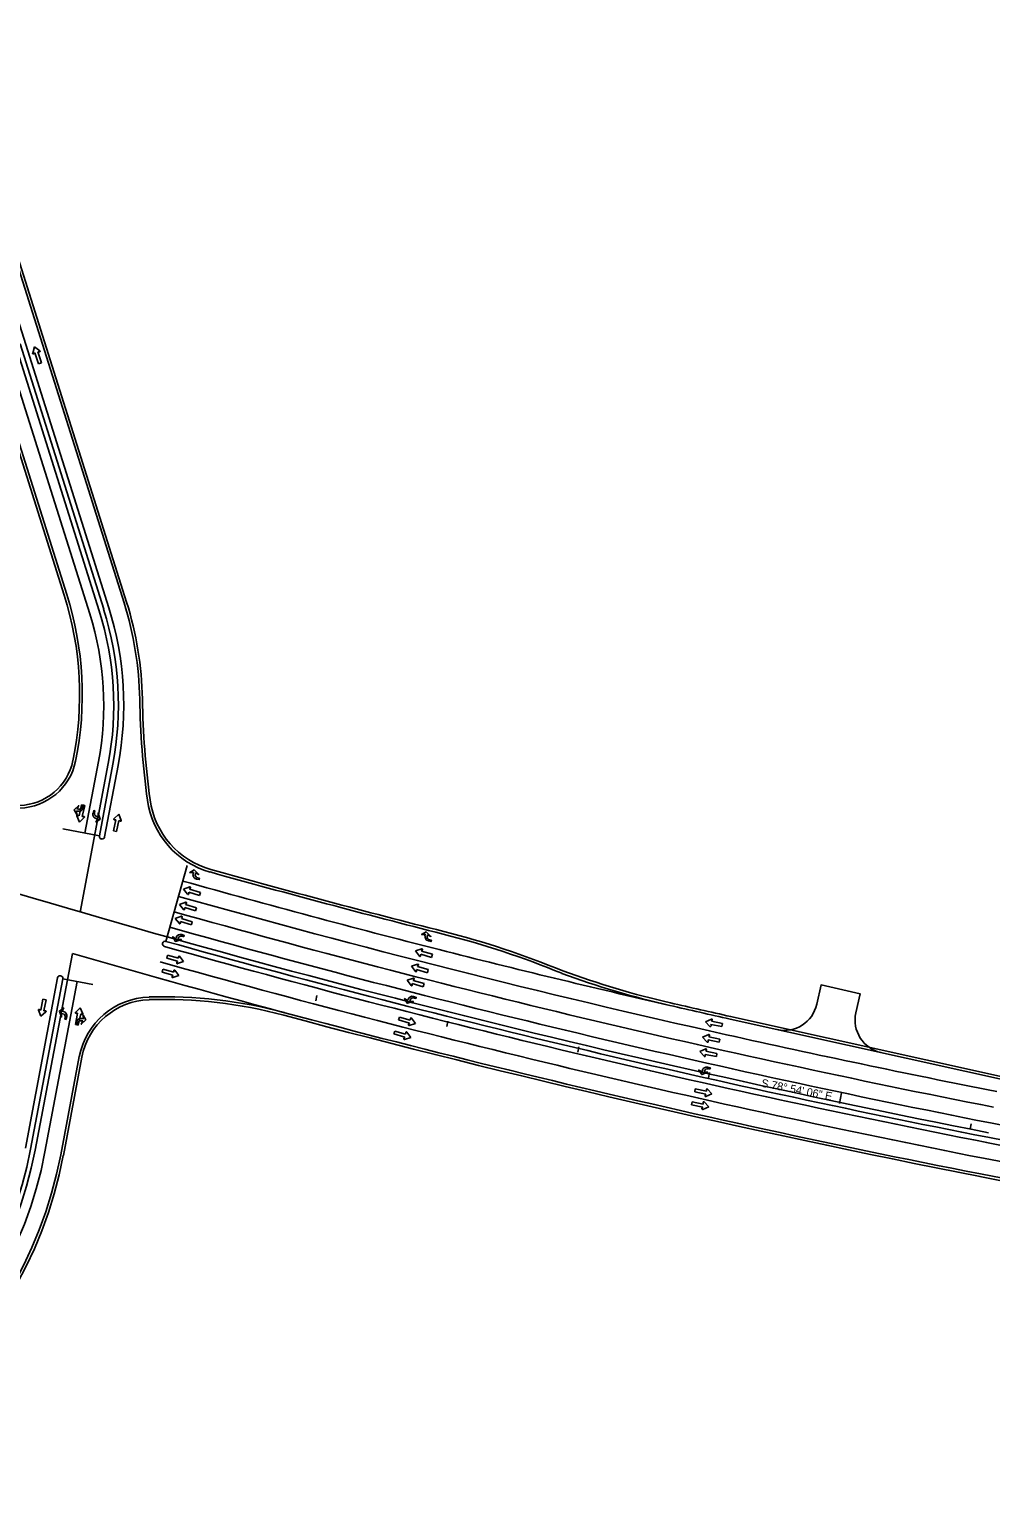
# Model space of a CAD drawing. Extents: x 1936748 to 1944587, y 778949 to 784066.
# Drawn here: x 1942950 to 1943671, y 779696 to 780801 of the extents above; entities that cross this region are included whole.
import ezdxf

# ---------------------------------------------------------------- set-up
doc = ezdxf.new("R2010")
doc.units = 0
for name, color, linetype in [('Default', 7, 'Continuous'), ('RD_HC_CL_Rel', 7, 'Continuous'), ('RD_HC_Data', 7, 'Continuous'), ('RD_HC_Data_Tic', 7, 'Continuous'), ('RD_PD_ALT1_LnLine', 7, 'Continuous'), ('RD_PD_ALT2_LnLine', 7, 'Continuous'), ('RD_PD_ALT3_LnLine', 7, 'Continuous'), ('RD_PD_Driveway', 7, 'Continuous'), ('RD_PD_Final_TrvlWay', 7, 'Continuous'), ('RD_PD_PaveShd', 7, 'Continuous')]:
    doc.layers.add(name, color=color, linetype=linetype)

msp = doc.modelspace()

# ---------------------------------------------------------------- linework, layer by layer
at = {"layer": 'Default'}
for p, q in [((1942953.8, 780563.7), (1942952.4, 780558.9)), ((1942953, 780558.4), (1942954.1, 780559.1)), ((1942957.8, 780560.7), (1942953.8, 780563.7)), ((1942954.1, 780559.1), (1942956.7, 780551)), ((1942956.3, 780559.8), (1942957.6, 780559.9)), ((1942958.9, 780551.7), (1942956.3, 780559.8)), ((1942957.8, 780560.7), (1942957.8, 780560.7)), ((1942956.7, 780551), (1942958.9, 780551.7)), ((1942989.1, 780220.3), (1942987.2, 780212)), ((1942991.4, 780219.8), (1942989.1, 780220.3)), ((1942989.4, 780218.9), (1942989.7, 780220.2)), ((1942989.5, 780211.5), (1942991.4, 780219.8)), ((1942998.8, 780214.4), (1942999.1, 780215.8)), ((1942985.5, 780212), (1942987.4, 780207.4)), ((1942985.5, 780212), (1942985.5, 780212)), ((1942987.2, 780212), (1942986.1, 780212.6)), ((1942987.4, 780207.4), (1942991, 780210.8)), ((1942990.7, 780211.5), (1942989.5, 780211.5)), ((1943014.8, 780209.2), (1943013, 780200.9)), ((1943017, 780213.3), (1943013.3, 780209.9)), ((1943013.6, 780209.2), (1943014.8, 780209.2)), ((1943015.2, 780200.4), (1943017.1, 780208.7)), ((1943018.8, 780208.7), (1943017, 780213.3)), ((1943017.1, 780208.7), (1943018.3, 780208.1)), ((1943018.8, 780208.7), (1943018.8, 780208.7)), ((1943013, 780200.9), (1943015.2, 780200.4)), ((1943070.3, 780158.8), (1943065.5, 780157.2)), ((1943070.3, 780158.8), (1943070.3, 780158.8)), ((1943076.2, 780165.6), (1943077.5, 780165.3)), ((1943065.5, 780157.2), (1943068.6, 780153.3)), ((1943069.4, 780153.6), (1943069.5, 780154.8)), ((1943069.5, 780154.8), (1943077.6, 780152.4)), ((1943070.1, 780157.1), (1943070.8, 780158.2)), ((1943078.3, 780154.7), (1943070.1, 780157.1)), ((1943077.6, 780152.4), (1943078.3, 780154.7)), ((1943064, 780136.8), (1943059.3, 780135.2)), ((1943067.2, 780147.3), (1943062.5, 780145.7)), ((1943062.5, 780145.7), (1943065.6, 780141.8)), ((1943064, 780136.8), (1943064, 780136.8)), ((1943066.3, 780142.1), (1943066.4, 780143.3)), ((1943066.4, 780143.3), (1943074.6, 780140.9)), ((1943067.1, 780145.6), (1943067.7, 780146.7)), ((1943075.2, 780143.2), (1943067.1, 780145.6)), ((1943067.2, 780147.3), (1943067.2, 780147.3)), ((1943074.6, 780140.9), (1943075.2, 780143.2)), ((1943059.3, 780135.2), (1943062.4, 780131.3)), ((1943063.2, 780131.6), (1943063.2, 780132.9)), ((1943063.2, 780132.9), (1943071.4, 780130.4)), ((1943063.9, 780135.1), (1943064.5, 780136.2)), ((1943072.1, 780132.7), (1943063.9, 780135.1)), ((1943071.4, 780130.4), (1943072.1, 780132.7)), ((1943064.5, 780121.9), (1943065.8, 780121.5)), ((1943250.1, 780119.2), (1943251.4, 780118.9)), ((1943053.5, 780107.7), (1943052.9, 780105.5)), ((1943052.9, 780105.5), (1943061, 780103.1)), ((1943061.7, 780105.3), (1943053.5, 780107.7)), ((1943061.8, 780106.5), (1943061.7, 780105.3)), ((1943065.6, 780102.9), (1943062.5, 780106.8)), ((1943244.2, 780112.4), (1943239.5, 780110.8)), ((1943239.5, 780110.8), (1943242.6, 780106.9)), ((1943243.3, 780107.2), (1943243.4, 780108.5)), ((1943243.4, 780108.5), (1943251.6, 780106)), ((1943244, 780110.7), (1943244.7, 780111.8)), ((1943252.2, 780108.3), (1943244, 780110.7)), ((1943244.2, 780112.4), (1943244.2, 780112.4)), ((1943251.6, 780106), (1943252.2, 780108.3)), ((1943050, 780097.2), (1943049.4, 780095)), ((1943049.4, 780095), (1943057.5, 780092.6)), ((1943058.2, 780094.8), (1943050, 780097.2)), ((1943057.5, 780092.6), (1943056.9, 780091.5)), ((1943057.4, 780090.9), (1943062.1, 780092.4)), ((1943058.3, 780096), (1943058.2, 780094.8)), ((1943062.1, 780092.4), (1943059, 780096.3)), ((1943061, 780103.1), (1943060.4, 780102)), ((1943060.9, 780101.3), (1943065.6, 780102.9)), ((1943060.9, 780101.3), (1943060.9, 780101.3)), ((1943241.1, 780100.9), (1943236.4, 780099.3)), ((1943236.4, 780099.3), (1943239.5, 780095.4)), ((1943240.3, 780095.7), (1943240.3, 780096.9)), ((1943240.3, 780096.9), (1943248.5, 780094.5)), ((1943241, 780099.2), (1943241.6, 780100.3)), ((1943249.1, 780096.8), (1943241, 780099.2)), ((1943241.1, 780100.9), (1943241.1, 780100.9)), ((1943248.5, 780094.5), (1943249.1, 780096.8)), ((1943057.4, 780090.9), (1943057.4, 780090.9)), ((1943237.9, 780090.4), (1943233.2, 780088.8)), ((1943233.2, 780088.8), (1943236.3, 780085)), ((1943237.1, 780085.2), (1943237.1, 780086.5)), ((1943237.1, 780086.5), (1943245.3, 780084)), ((1943237.8, 780088.7), (1943238.4, 780089.8)), ((1943246, 780086.3), (1943237.8, 780088.7)), ((1943237.9, 780090.4), (1943237.9, 780090.4)), ((1943245.3, 780084), (1943246, 780086.3)), ((1942960.1, 780074.8), (1942958.4, 780066.4)), ((1942962.4, 780074.3), (1942960.1, 780074.8)), ((1942960.7, 780066), (1942962.4, 780074.3)), ((1943238.4, 780075.5), (1943239.7, 780075.1)), ((1942956.7, 780066.4), (1942958.6, 780061.9)), ((1942956.7, 780066.4), (1942956.7, 780066.4)), ((1942958.4, 780066.4), (1942957.3, 780067)), ((1942958.6, 780061.9), (1942962.3, 780065.3)), ((1942961.9, 780066), (1942960.7, 780066)), ((1942976.8, 780061), (1942976.5, 780059.7)), ((1942986.1, 780064.1), (1942984.4, 780055.8)), ((1942988.1, 780068.2), (1942984.5, 780064.8)), ((1942984.8, 780064.1), (1942986.1, 780064.1)), ((1942986.6, 780055.3), (1942988.4, 780063.7)), ((1942990.1, 780063.7), (1942988.1, 780068.2)), ((1942988.4, 780063.7), (1942989.5, 780063.1)), ((1942990.1, 780063.7), (1942990.1, 780063.7)), ((1943227.5, 780061.3), (1943226.8, 780059.1)), ((1943226.8, 780059.1), (1943235, 780056.7)), ((1943235.6, 780058.9), (1943227.5, 780061.3)), ((1943235.7, 780060.1), (1943235.6, 780058.9)), ((1943239.6, 780056.5), (1943236.5, 780060.4)), ((1943461.4, 780059.8), (1943456.9, 780057.8)), ((1943461.4, 780059.8), (1943461.4, 780059.8)), ((1943461.5, 780058.1), (1943462, 780059.2)), ((1942984.4, 780055.8), (1942986.6, 780055.3)), ((1942986.3, 780056.8), (1942986, 780055.4)), ((1943224, 780050.8), (1943223.3, 780048.6)), ((1943223.3, 780048.6), (1943231.5, 780046.2)), ((1943232.1, 780048.4), (1943224, 780050.8)), ((1943232.2, 780049.7), (1943232.1, 780048.4)), ((1943236, 780046), (1943232.9, 780049.9)), ((1943235, 780056.7), (1943234.3, 780055.6)), ((1943234.8, 780055), (1943239.6, 780056.5)), ((1943234.8, 780055), (1943234.8, 780055)), ((1943459.4, 780048.1), (1943454.8, 780046.1)), ((1943456.9, 780057.8), (1943460.3, 780054.2)), ((1943459.4, 780048.1), (1943459.4, 780048.1)), ((1943461.1, 780054.6), (1943461, 780055.8)), ((1943461, 780055.8), (1943469.3, 780054.1)), ((1943469.8, 780056.4), (1943461.5, 780058.1)), ((1943469.3, 780054.1), (1943469.8, 780056.4)), ((1943231.5, 780046.2), (1943230.8, 780045.1)), ((1943231.3, 780044.5), (1943236, 780046)), ((1943231.3, 780044.5), (1943231.3, 780044.5)), ((1943457.2, 780037.4), (1943452.6, 780035.4)), ((1943454.8, 780046.1), (1943458.3, 780042.5)), ((1943457.2, 780037.4), (1943457.2, 780037.4)), ((1943459, 780042.8), (1943459, 780044.1)), ((1943459, 780044.1), (1943467.3, 780042.4)), ((1943459.4, 780046.4), (1943460, 780047.5)), ((1943467.8, 780044.7), (1943459.4, 780046.4)), ((1943467.3, 780042.4), (1943467.8, 780044.7)), ((1943452.6, 780035.4), (1943456.1, 780031.8)), ((1943456.8, 780032.1), (1943456.7, 780033.3)), ((1943456.7, 780033.3), (1943465.1, 780031.7)), ((1943457.2, 780035.6), (1943457.7, 780036.8)), ((1943465.5, 780033.9), (1943457.2, 780035.6)), ((1943465.1, 780031.7), (1943465.5, 780033.9)), ((1943459, 780022.6), (1943460.3, 780022.2)), ((1943449.3, 780007.4), (1943448.9, 780005.2)), ((1943448.9, 780005.2), (1943457.2, 780003.5)), ((1943457.7, 780005.8), (1943449.3, 780007.4)), ((1943457.2, 780001.7), (1943461.8, 780003.7)), ((1943457.6, 780007), (1943457.7, 780005.8)), ((1943461.8, 780003.7), (1943458.4, 780007.3)), ((1943447, 779997.8), (1943446.5, 779995.5)), ((1943446.5, 779995.5), (1943454.9, 779993.8)), ((1943455.3, 779996.1), (1943447, 779997.8)), ((1943454.9, 779993.8), (1943454.3, 779992.7)), ((1943454.9, 779992.1), (1943459.4, 779994.1)), ((1943455.3, 779997.4), (1943455.3, 779996.1)), ((1943459.4, 779994.1), (1943456, 779997.7)), ((1943457.2, 780003.5), (1943456.7, 780002.3)), ((1943457.2, 780001.7), (1943457.2, 780001.7)), ((1943454.9, 779992.1), (1943454.9, 779992.1))]:
    msp.add_line(p, q, dxfattribs=at)
for points in [[(1942986.3, 780215.5), (1942985.3, 780215.7), (1942985.4, 780213), (1942983.4, 780216.5), (1942986.9, 780219.8), (1942985.7, 780217.3), (1942986.7, 780217.1)], [(1942989.7, 780220.2), (1942990.7, 780220), (1942990.3, 780218)], [(1942999.1, 780215.8), (1942998.2, 780216), (1942997.7, 780214)], [(1943000, 780210), (1943001.1, 780209.8), (1942999.8, 780207.4), (1943003.1, 780209.6), (1943001.5, 780214.2), (1943001.5, 780211.4), (1943000.5, 780211.7)], [(1943072.7, 780168.6), (1943072.9, 780169.6), (1943070.2, 780169.5), (1943073.6, 780171.5), (1943077, 780168.1), (1943074.6, 780169.3), (1943074.4, 780168.3)], [(1943077.5, 780165.3), (1943077.3, 780164.3), (1943075.3, 780164.7)], [(1943060, 780121), (1943059.7, 780120), (1943057.4, 780121.5), (1943059.4, 780118), (1943064, 780119.3), (1943061.3, 780119.5), (1943061.6, 780120.5)], [(1943065.8, 780121.5), (1943066.1, 780122.4), (1943064.2, 780123.1)], [(1943246.6, 780122.2), (1943246.8, 780123.2), (1943244.1, 780123.1), (1943247.6, 780125.1), (1943251, 780121.7), (1943248.5, 780122.9), (1943248.3, 780121.9)], [(1943251.4, 780118.9), (1943251.2, 780117.9), (1943249.2, 780118.3)], [(1943234, 780074.6), (1943233.6, 780073.6), (1943231.3, 780075.1), (1943233.3, 780071.6), (1943237.9, 780072.9), (1943235.2, 780073.1), (1943235.5, 780074.1)], [(1943239.7, 780075.1), (1943240.1, 780076), (1943238.1, 780076.7)], [(1942975.5, 780065.4), (1942974.5, 780065.6), (1942975.7, 780068.1), (1942972.4, 780065.8), (1942974.1, 780061.3), (1942974.1, 780064), (1942975.1, 780063.8)], [(1942976.5, 780059.7), (1942977.5, 780059.5), (1942977.9, 780061.5)], [(1942989.3, 780060.2), (1942990.3, 780060), (1942990.2, 780062.7), (1942992.2, 780059.3), (1942988.8, 780055.9), (1942990, 780058.4), (1942989, 780058.6)], [(1942986, 780055.4), (1942985, 780055.6), (1942985.4, 780057.7)], [(1943454.6, 780021.3), (1943454.4, 780020.2), (1943451.9, 780021.5), (1943454.2, 780018.2), (1943458.7, 780019.9), (1943456, 780019.9), (1943456.2, 780020.9)], [(1943460.3, 780022.2), (1943460.6, 780023.2), (1943458.6, 780023.7)]]:
    msp.add_lwpolyline(points, dxfattribs=at)
for centre, radius, start, end in [((1942952.8, 780558.8), 0.443, 162.8279, 303.291), ((1942957.5, 780560.3), 0.443, 272.6168, 53.103), ((1942987.1, 780218.7), 3.28, 257.287, 347.287), ((1942987.2, 780219.4), 2.3, 257.287, 347.287), ((1943000.8, 780213.2), 3.28, 165.8722, 255.8722), ((1943001, 780213.9), 2.3, 165.8722, 255.8722), ((1942985.9, 780212.2), 0.443, 61.9969, 202.4831), ((1942990.8, 780211.1), 0.443, 312.208, 92.6711), ((1943013.6, 780209.6), 0.443, 132.208, 272.6711), ((1943018.4, 780208.5), 0.443, 241.9969, 22.4831), ((1943070.4, 780158.4), 0.443, 328.1928, 108.6791), ((1943075.9, 780167.9), 3.28, 168.7617, 258.7617), ((1943076.6, 780167.8), 2.3, 168.7617, 258.7617), ((1943069, 780153.6), 0.443, 218.4039, 358.867), ((1943064.2, 780136.4), 0.443, 328.1928, 108.6791), ((1943065.9, 780142.1), 0.443, 218.4039, 358.867), ((1943067.3, 780146.9), 0.443, 328.1928, 108.6791), ((1943062.7, 780131.6), 0.443, 218.4039, 358.867), ((1943063.1, 780120), 3.28, 71.3683, 161.3683), ((1943063.8, 780119.7), 2.3, 71.3683, 161.3683), ((1943249.9, 780121.6), 3.28, 168.7617, 258.7617), ((1943250.5, 780121.4), 2.3, 168.7617, 258.7617), ((1943062.2, 780106.5), 0.443, 38.4039, 178.867), ((1943242.9, 780107.2), 0.443, 218.4039, 358.867), ((1943244.3, 780112), 0.443, 328.1928, 108.6791), ((1943058.7, 780096.1), 0.443, 38.4039, 178.867), ((1943060.8, 780101.7), 0.443, 148.1928, 288.6791), ((1943239.8, 780095.7), 0.443, 218.4039, 358.867), ((1943241.3, 780100.5), 0.443, 328.1928, 108.6791), ((1943057.3, 780091.3), 0.443, 148.1928, 288.6791), ((1943236.7, 780085.2), 0.443, 218.4039, 358.867), ((1943238.1, 780090), 0.443, 328.1928, 108.6791), ((1943237.1, 780073.6), 3.28, 71.3683, 161.3683), ((1943237.7, 780073.3), 2.3, 71.3683, 161.3683), ((1942957.1, 780066.6), 0.443, 63.0465, 203.5327), ((1942962, 780065.6), 0.443, 313.2576, 93.7207), ((1942974.6, 780061.5), 2.3, 346.9217, 76.9217), ((1942974.8, 780062.2), 3.28, 346.9217, 76.9217), ((1942984.8, 780064.5), 0.443, 133.2576, 273.7207), ((1942988.6, 780057), 3.28, 78.3365, 168.3365), ((1942989.7, 780063.5), 0.443, 243.0465, 23.5327), ((1943236.1, 780060.2), 0.443, 38.4039, 178.867), ((1943461.6, 780059.4), 0.443, 333.301, 113.7872), ((1942988.5, 780056.3), 2.3, 78.3365, 168.3365), ((1943232.6, 780049.7), 0.443, 38.4039, 178.867), ((1943234.7, 780055.4), 0.443, 148.1928, 288.6791), ((1943459.6, 780047.7), 0.443, 333.301, 113.7872), ((1943460.6, 780054.5), 0.443, 223.5121, 3.9752), ((1943231.2, 780044.9), 0.443, 148.1928, 288.6791), ((1943457.4, 780037), 0.443, 333.301, 113.7872), ((1943458.6, 780042.8), 0.443, 223.5121, 3.9752), ((1943456.4, 780032.1), 0.443, 223.5121, 3.9752), ((1943457.8, 780020.5), 3.28, 76.4764, 166.4764), ((1943458.5, 780020.3), 2.3, 76.4764, 166.4764), ((1943458.1, 780007), 0.443, 43.5121, 183.9752), ((1943454.7, 779992.5), 0.443, 153.301, 293.7872), ((1943455.7, 779997.4), 0.443, 43.5121, 183.9752), ((1943457.1, 780002.1), 0.443, 153.301, 293.7872)]:
    msp.add_arc(centre, radius, start, end, dxfattribs=at)
at = {"layer": 'RD_HC_CL_Rel'}
for p, q in [((1942610.6, 781606.5), (1943002.3, 780365.8)), ((1943009.1, 780251.3), (1942988, 780140)), ((1942982.2, 780108.9), (1942954.2, 779961.6))]:
    msp.add_line(p, q, dxfattribs=at)
for centre, radius, start, end in [((1942778.2, 780295.1), 235, 349.2715, 17.5247), ((1945184.2, 787697.4), 7870, 252.6501, 258.90156), ((1942659.5, 780017.4), 300, 267.5865, 349.2715)]:
    msp.add_arc(centre, radius, start, end, dxfattribs=at)
at = {"layer": 'RD_HC_Data_Tic'}
for p, q in [((1943164.8, 780073.5), (1943165.6, 780077.5)), ((1943263, 780054.3), (1943263.7, 780058.2)), ((1943361.1, 780035), (1943361.9, 780039)), ((1943459.2, 780015.8), (1943460, 780019.7)), ((1943557.4, 779996.5), (1943558.9, 780004.4)), ((1943655.5, 779977.3), (1943656.3, 779981.2))]:
    msp.add_line(p, q, dxfattribs=at)
at = {"layer": 'RD_PD_ALT1_LnLine'}
for p, q in [((1942932.4, 780562.4), (1942995.2, 780363.6)), ((1943001.8, 780252.7), (1942991.6, 780199.1)), ((1942985.8, 780087.9), (1942961.6, 779960.2)), ((1943670.7, 779981.9), (1943888.6, 779939.2)), ((1943665.5, 779955.5), (1944051.2, 779879.8))]:
    msp.add_line(p, q, dxfattribs=at)
for centre, radius, start, end in [((1942778.2, 780295.1), 227.5, 349.2715, 17.5247), ((1945184.2, 787697.4), 7826.5, 254.29042, 255.74647), ((1945184.2, 787697.4), 7838.5, 254.29042, 257.38869), ((1945184.2, 787697.4), 7850.5, 254.29042, 258.90156), ((1945184.2, 787697.4), 7862.5, 254.29042, 258.90156), ((1945184.2, 787697.4), 7826.5, 255.74647, 257.04964), ((1945184.2, 787697.4), 7889.5, 254.29042, 258.90156), ((1945184.2, 787697.4), 7838.5, 257.38869, 258.90156), ((1942659.5, 780017.4), 307.5, 267.5865, 349.2715)]:
    msp.add_arc(centre, radius, start, end, dxfattribs=at)
at = {"layer": 'RD_PD_ALT2_LnLine'}
for p, q in [((1943002.4, 780197.1), (1942975, 780202.3)), ((1943052.3, 780118), (1943068.3, 780174.8)), ((1942975, 780089.9), (1942997.6, 780085.7))]:
    msp.add_line(p, q, dxfattribs=at)
at = {"layer": 'RD_PD_ALT3_LnLine'}
for p, q in [((1942880.1, 780777.7), (1943009.5, 780368.1)), ((1942942.9, 780565.8), (1943005.7, 780366.9)), ((1943012.6, 780250.7), (1943002.4, 780197.1)), ((1943016.5, 780249.9), (1943006.3, 780196.3)), ((1942971.1, 780090.7), (1942946.9, 779963)), ((1942975, 780089.9), (1942950.8, 779962.2)), ((1943668.6, 779971.2), (1943886.4, 779928.4)), ((1943667.8, 779967.2), (1944053.5, 779891.6))]:
    msp.add_line(p, q, dxfattribs=at)
for centre, radius, start, end in [((1942778.2, 780295.1), 238.5, 349.2715, 17.5247), ((1942778.2, 780295.1), 242.5, 349.2715, 17.5247), ((1943004.4, 780196.7), 2, 169.2715, 349.2715), ((1943051.8, 780116.1), 2, 74.2904, 254.2904), ((1945184.2, 787697.4), 7873.5, 254.29042, 258.90156), ((1945184.2, 787697.4), 7877.5, 254.29042, 258.90156), ((1942973, 780090.3), 2, 349.2715, 169.2715), ((1942659.5, 780017.4), 296.5, 267.5865, 349.2715)]:
    msp.add_arc(centre, radius, start, end, dxfattribs=at)
at = {"layer": 'RD_PD_Driveway'}
msp.add_lwpolyline([(1943540.4, 780070.9), (1943543.6, 780085.3), (1943572.9, 780078.8), (1943569.7, 780064.4)], dxfattribs=at)
for centre, start, end in [((1943516, 780076.3), 257.4946, 347.4946), ((1943594.1, 780059), 167.4946, 257.4946)]:
    msp.add_arc(centre, 25, start, end, dxfattribs=at)
at = {"layer": 'RD_PD_Final_TrvlWay'}
for p, q in [((1942891.5, 780781.5), (1943020.9, 780371.7)), ((1942854.3, 780769.7), (1942978, 780378.1)), ((1943475.4, 780059.7), (1944061, 779929.8)), ((1942987.3, 780031.6), (1942973.4, 779957.9)), ((1943663.2, 779943.7), (1944048.9, 779868))]:
    msp.add_line(p, q, dxfattribs=at)
for centre, radius, start, end in [((1942739.6, 780302.8), 250, 348.5083, 17.5247), ((1942778.2, 780295.1), 254.5, 0.9931, 17.5247), ((1943672.6, 780310.6), 640, 180.9931, 187.7904), ((1942941.5, 780261.8), 43.9, 271.5515, 348.5083), ((1943102.9, 780232.6), 65, 187.7904, 254.4209), ((1945184.2, 787697.4), 7814.5, 254.42086, 255.74647), ((1943095.2, 779474.1), 670, 67.716, 75.7465), ((1945184.2, 787697.4), 7901.5, 253.81826, 258.90156), ((1943580.4, 780722.9), 670, 249.8217, 257.0496), ((1943041.4, 780021.3), 55, 91.8035, 169.2715), ((1943050.7, 779726.5), 350, 75.0153, 91.8035), ((1945184.2, 787697.4), 7826.5, 257.04964, 257.38869), ((1942659.5, 780017.4), 319.5, 267.5865, 349.2715)]:
    msp.add_arc(centre, radius, start, end, dxfattribs=at)
at = {"layer": 'RD_PD_PaveShd'}
for p, q in [((1942893.4, 780782.1), (1943022.8, 780372.3)), ((1942852.4, 780769.1), (1942976.1, 780377.5)), ((1943475.8, 780061.7), (1944061.4, 779931.8)), ((1942989.3, 780031.2), (1942975.4, 779957.6)), ((1943662.8, 779941.7), (1944048.5, 779866.1))]:
    msp.add_line(p, q, dxfattribs=at)
for centre, radius, start, end in [((1942739.6, 780302.8), 248, 348.5083, 17.5247), ((1942778.2, 780295.1), 256.5, 0.9931, 17.5247), ((1943672.6, 780310.6), 638, 180.9931, 187.7904), ((1942941.5, 780261.8), 41.9, 271.5515, 348.5083), ((1943102.9, 780232.6), 63, 187.7904, 254.4209), ((1945184.2, 787697.4), 7812.5, 254.42086, 255.74647), ((1943095.2, 779474.1), 672, 67.716, 75.7465), ((1943580.4, 780722.9), 668, 249.8217, 257.0496), ((1943041.4, 780021.3), 53, 91.8035, 169.2715), ((1943050.7, 779726.5), 348, 75.0153, 91.8035), ((1945184.2, 787697.4), 7824.5, 257.04964, 257.38869), ((1945184.2, 787697.4), 7903.5, 255.01531, 258.90156), ((1942659.5, 780017.4), 321.5, 267.5865, 349.2715)]:
    msp.add_arc(centre, radius, start, end, dxfattribs=at)

# ---------------------------------------------------------------- texts
at = {"layer": 'RD_HC_Data'}
msp.add_text('S 78%%d 54\' 06" E', height=6, rotation=348.9016, dxfattribs=at).set_placement((1943498.4, 780009.1))

doc.saveas('drawing.dxf')
